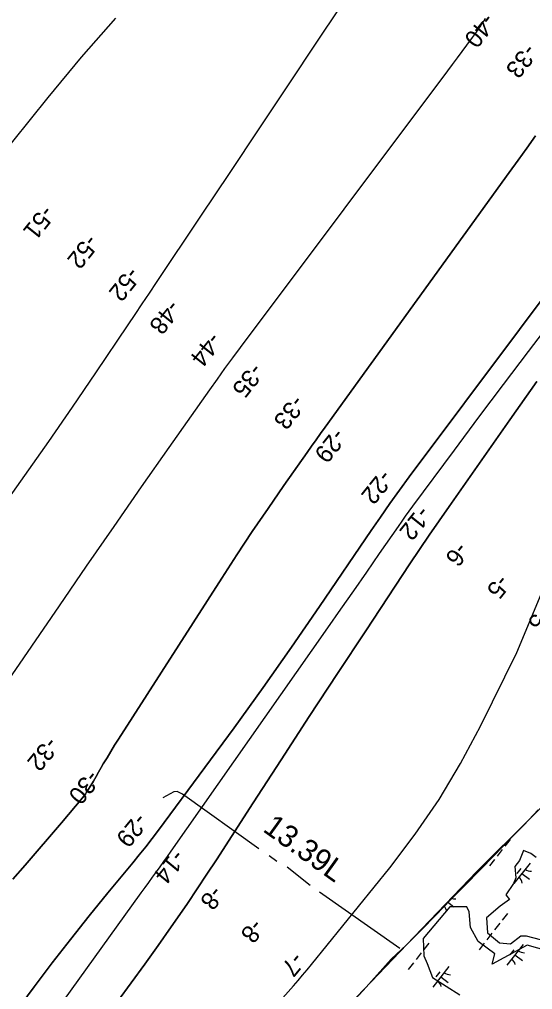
# Model space of a CAD drawing. Extents: x 3896831 to 3918110, y 171006 to 193349.
# Drawn here: x 3909708 to 3910688, y 181692 to 183545 of the extents above; entities that cross this region are included whole.
import ezdxf

# ---------------------------------------------------------------- set-up
doc = ezdxf.new("R2010")
doc.units = 0
for name, color, linetype in [('V-GRID-MAJR', 7, 'Continuous'), ('V-LEVE-TOET', 7, 'Continuous'), ('V-RIVR-EDGE', 7, 'Continuous'), ('V-RIVR-RANG', 7, 'Continuous'), ('V-RRAP-FSHR', 7, 'Continuous'), ('V-STRM-FMON', 7, 'Continuous'), ('V-TOPO-DPTH', 7, 'Continuous'), ('V-TOPO-MAJR', 7, 'Continuous'), ('V-TOPO-MINR', 7, 'Continuous'), ('V-WETL-SWMP', 7, 'Continuous')]:
    doc.layers.add(name, color=color, linetype=linetype)

msp = doc.modelspace()

# ---------------------------------------------------------------- linework, layer by layer
at = {"layer": 'V-GRID-MAJR'}
msp.add_spline([(3909752.8, 175802), (3909660.5, 181175.4), (3909556.5, 187235.6), (3909500.7, 190486.2)], degree=3, dxfattribs=at)
at = {"layer": 'V-LEVE-TOET'}
for p, q in [((3910200.2, 181936.9), (3910185.5, 181947.9)), ((3910263.7, 181891.2), (3910219.7, 181925.8)), ((3910434.7, 181770.8), (3910281.5, 181878.1))]:
    msp.add_line(p, q, dxfattribs=at)
msp.add_lwpolyline([(3910165.8, 181961.2), (3910019.7, 182065.5), (3910009.4, 182070.4), (3910003, 182070), (3909982, 182058.3)], dxfattribs=at)
at = {"layer": 'V-RIVR-EDGE'}
for points in [[(3910694.8, 181944.3), (3910684.7, 181952.2), (3910671.1, 181957.9), (3910663.2, 181938.7), (3910654.2, 181927.4), (3910656.4, 181905.9), (3910651.9, 181894.7), (3910637.3, 181873.2), (3910644, 181864.2), (3910626, 181851.8), (3910600, 181829.2), (3910602.3, 181801), (3910624.8, 181781.8), (3910646.3, 181779.5), (3910665.5, 181795.3), (3910675.6, 181795.3), (3910717.4, 181784.1)], [(3910718.5, 181766), (3910677.9, 181777.3), (3910611.3, 181741.2), (3910615.8, 181760.4), (3910584.2, 181784.1), (3910569.5, 181811.1), (3910567.3, 181840.5), (3910562.8, 181850.6), (3910530, 181850.6), (3910479.3, 181789.7), (3910480.4, 181757), (3910487.2, 181742.3), (3910497.3, 181715.2), (3910549.2, 181682.5)]]:
    msp.add_lwpolyline(points, dxfattribs=at)
at = {"layer": 'V-RRAP-FSHR'}
msp.add_lwpolyline([(3910095.3, 181395.6), (3910122.2, 181424.6), (3910149.2, 181454.2), (3910176.1, 181483.7), (3910203.1, 181513.2), (3910230.4, 181542.8), (3910256.9, 181572.4), (3910283.8, 181602.4), (3910310.7, 181631.6), (3910337.6, 181661.3), (3910364.5, 181690.9), (3910391.4, 181720.5), (3910418.3, 181750.7), (3910447.4, 181777.5), (3910475.5, 181805.9), (3910503.5, 181834.5), (3910531.5, 181863.6), (3910559.5, 181891.7), (3910587.4, 181920.4), (3910615.3, 181949.2), (3910643.1, 181977.7), (3910671.4, 182006.4), (3910698.9, 182035.3)], dxfattribs=at)
at = {"layer": 'V-TOPO-DPTH'}
for points in [[(3909679.6, 182271), (3909784.7, 182424.7), (3909836.8, 182500.7), (3909889.2, 182576.5), (3909941.8, 182652.1), (3909994.6, 182727.6), (3910071.8, 182837.4), (3910086.3, 182857.8), (3910100.9, 182878.1), (3910115.7, 182898.3), (3910130.7, 182918.4), (3910526.2, 183446.5), (3910535.4, 183458.7), (3910544.5, 183471), (3910553.6, 183483.3), (3910562.7, 183495.5), (3910573.3, 183509.9), (3910577.1, 183515), (3910580.8, 183520.2), (3910584.4, 183525.4), (3910587.9, 183530.7), (3910591.5, 183536), (3910595, 183541.3), (3910598.5, 183546.7)], [(3909679.6, 182271), (3909784.7, 182424.7), (3909836.8, 182500.7), (3909889.2, 182576.5), (3909941.8, 182652.1), (3909994.6, 182727.6), (3910071.8, 182837.4), (3910086.3, 182857.8), (3910100.9, 182878.1), (3910115.7, 182898.3), (3910130.7, 182918.4), (3910526.2, 183446.5), (3910535.4, 183458.7), (3910544.5, 183471), (3910553.6, 183483.3), (3910562.7, 183495.5), (3910573.3, 183509.9), (3910577.1, 183515), (3910580.8, 183520.2), (3910584.4, 183525.4), (3910587.9, 183530.7), (3910591.5, 183536), (3910595, 183541.3), (3910598.5, 183546.7)], [(3909695.8, 181903.2), (3909719.3, 181929.9), (3909742.6, 181956.7), (3909765.8, 181983.7), (3909788.8, 182010.8), (3909828.7, 182058.2), (3909831.6, 182061.8), (3909834.3, 182065.4), (3909836.8, 182069.2), (3909839.3, 182073), (3909844.7, 182082.1), (3909849.7, 182090.5), (3909854.7, 182099), (3909859.7, 182107.5), (3909864.6, 182116.1), (3909868.6, 182123.1), (3909875.7, 182135.1), (3909882.8, 182147.1), (3909890.1, 182158.9), (3909897.5, 182170.7), (3910094.6, 182477.8), (3910123.7, 182522.5), (3910153.1, 182567), (3910183.1, 182611), (3910213.4, 182654.9), (3910257.7, 182718), (3910266.2, 182730.1), (3910274.7, 182742.1), (3910283.3, 182754.1), (3910291.9, 182766.1), (3910643.6, 183252.5), (3910660.4, 183275.7), (3910677.2, 183299), (3910693.9, 183322.2)], [(3910693.9, 183322.2), (3910677.2, 183299), (3910660.4, 183275.7), (3910643.6, 183252.5), (3910291.9, 182766.1), (3910283.3, 182754.1), (3910274.7, 182742.1), (3910266.2, 182730.1), (3910257.7, 182718), (3910213.4, 182654.9), (3910183.1, 182611), (3910153.1, 182567), (3910123.7, 182522.5), (3910094.6, 182477.8), (3909897.5, 182170.7), (3909890.1, 182158.9), (3909882.8, 182147.1), (3909875.7, 182135.1), (3909868.6, 182123.1), (3909864.6, 182116.1), (3909859.7, 182107.5), (3909854.7, 182099), (3909849.7, 182090.5), (3909844.7, 182082.1), (3909839.3, 182073), (3909836.8, 182069.2), (3909834.3, 182065.4), (3909831.6, 182061.8), (3909828.7, 182058.2), (3909788.8, 182010.8), (3909765.8, 181983.7), (3909742.6, 181956.7), (3909719.3, 181929.9), (3909695.8, 181903.2)], [(3909520.4, 181405.9), (3909736.7, 181697.7), (3909771, 181743.2), (3909805.7, 181788.3), (3909841.3, 181832.9), (3909877.3, 181877), (3909924.7, 181934.2), (3909937.2, 181949.6), (3909949.6, 181965.1), (3909961.7, 181980.8), (3909973.7, 181996.6), (3910062.6, 182116.3), (3910118.5, 182192.4), (3910173.7, 182269), (3910227.9, 182346.3), (3910281.5, 182424), (3910379.8, 182568.7), (3910397.6, 182594.5), (3910415.7, 182620.3), (3910434.1, 182645.7), (3910452.8, 182671), (3910873.6, 183233.6)], [(3910873.6, 183233.6), (3910452.8, 182671), (3910434.1, 182645.7), (3910415.7, 182620.3), (3910397.6, 182594.5), (3910379.8, 182568.7), (3910281.5, 182424), (3910227.9, 182346.3), (3910173.7, 182269), (3910118.5, 182192.4), (3910062.6, 182116.3), (3909973.7, 181996.6), (3909961.7, 181980.8), (3909949.6, 181965.1), (3909937.2, 181949.6), (3909924.7, 181934.2), (3909877.3, 181877), (3909841.3, 181832.9), (3909805.7, 181788.3), (3909771, 181743.2), (3909736.7, 181697.7), (3909520.4, 181405.9)], [(3910696.1, 182853.3), (3910644.5, 182780.4), (3910528.6, 182614.9), (3910509.7, 182587.6), (3910490.9, 182560.2), (3910472.4, 182532.7), (3910453.9, 182505.1), (3910369.5, 182377.5), (3910315.5, 182295.6), (3910261.7, 182213.5), (3910208.1, 182131.3), (3910154.7, 182049), (3910084.4, 181940.3), (3910066.2, 181912.4), (3910047.8, 181884.6), (3910029.1, 181856.9), (3910010.2, 181829.5), (3909998.2, 181812.2), (3909973.1, 181776.4), (3909947.7, 181740.7), (3909921.9, 181705.2), (3909895.9, 181669.9)]]:
    msp.add_lwpolyline(points, dxfattribs=at)
at = {"layer": 'V-TOPO-MAJR'}
for points in [[(3909672.8, 182609), (3909719, 182673.7), (3909764.7, 182738.6), (3909809.8, 182804), (3909854.4, 182869.7), (3909915.9, 182961.3), (3909929.5, 182981.5), (3909943, 183001.7), (3909956.5, 183021.9), (3909970.1, 183042.1), (3910054.7, 183168.7), (3910110.5, 183252.2), (3910166.2, 183335.8), (3910221.9, 183419.4), (3910277.6, 183503), (3910361.5, 183629.2)], [(3909892, 183547.2), (3909826.4, 183472.3), (3909762.5, 183395.7), (3909661.1, 183269.5)]]:
    msp.add_lwpolyline(points, dxfattribs=at)
at = {"layer": 'V-TOPO-MINR'}
for points in [[(3909679.6, 182271), (3909784.7, 182424.7), (3909836.8, 182500.7), (3909889.2, 182576.5), (3909941.8, 182652.1), (3909994.6, 182727.6), (3910071.8, 182837.4), (3910086.3, 182857.8), (3910100.9, 182878.1), (3910115.7, 182898.3), (3910130.7, 182918.4), (3910526.2, 183446.5), (3910535.4, 183458.7), (3910544.5, 183471), (3910553.6, 183483.3), (3910562.7, 183495.5), (3910573.3, 183509.9), (3910577.1, 183515), (3910580.8, 183520.2), (3910584.4, 183525.4), (3910587.9, 183530.7), (3910591.5, 183536), (3910595, 183541.3), (3910598.5, 183546.7)], [(3909695.8, 181903.2), (3909719.3, 181929.9), (3909742.6, 181956.7), (3909765.8, 181983.7), (3909788.8, 182010.8), (3909828.7, 182058.2), (3909831.6, 182061.8), (3909834.3, 182065.4), (3909836.8, 182069.2), (3909839.3, 182073), (3909844.7, 182082.1), (3909849.7, 182090.5), (3909854.7, 182099), (3909859.7, 182107.5), (3909864.6, 182116.1), (3909868.6, 182123.1), (3909875.7, 182135.1), (3909882.8, 182147.1), (3909890.1, 182158.9), (3909897.5, 182170.7), (3910094.6, 182477.8), (3910123.7, 182522.5), (3910153.1, 182567), (3910183.1, 182611), (3910213.4, 182654.9), (3910257.7, 182718), (3910266.2, 182730.1), (3910274.7, 182742.1), (3910283.3, 182754.1), (3910291.9, 182766.1), (3910643.6, 183252.5), (3910660.4, 183275.7), (3910677.2, 183299), (3910693.9, 183322.2)], [(3909520.4, 181405.9), (3909736.7, 181697.7), (3909771, 181743.2), (3909805.7, 181788.3), (3909841.3, 181832.9), (3909877.3, 181877), (3909924.7, 181934.2), (3909937.2, 181949.6), (3909949.6, 181965.1), (3909961.7, 181980.8), (3909973.7, 181996.6), (3910062.6, 182116.3), (3910118.5, 182192.4), (3910173.7, 182269), (3910227.9, 182346.3), (3910281.5, 182424), (3910379.8, 182568.7), (3910397.6, 182594.5), (3910415.7, 182620.3), (3910434.1, 182645.7), (3910452.8, 182671), (3910873.6, 183233.6)], [(3909762.1, 181628), (3909941.2, 181877.3), (3909948.4, 181887.2), (3909955.5, 181897.1), (3909962.7, 181907), (3909969.9, 181916.9), (3909977, 181926.8), (3909984.2, 181936.7), (3909991.3, 181946.7), (3909998.3, 181956.7), (3910297, 182382.9), (3910321.8, 182418.4), (3910346.7, 182453.9), (3910371.4, 182489.5), (3910396.2, 182525.1), (3910432, 182576.7), (3910438.9, 182586.5), (3910445.8, 182596.2), (3910452.8, 182605.9), (3910459.8, 182615.5), (3910538.9, 182722.3), (3910585.7, 182785.1), (3910632.8, 182847.8), (3910680.1, 182910.3), (3910727.7, 182972.6)], [(3908993.8, 179918), (3909778.7, 181196.5), (3909782.4, 181202), (3909786.6, 181207.3), (3909882.7, 181311), (3909935.2, 181368.1), (3909987.5, 181425.3), (3910039.4, 181483), (3910091, 181540.8), (3910231.6, 181699.3), (3910240.4, 181709.4), (3910249.1, 181719.6), (3910257.8, 181729.8), (3910266.3, 181740.2), (3910415.7, 181924.6), (3910464.3, 181988.8), (3910509.8, 182055), (3910550.8, 182124.1), (3910588.8, 182195.1), (3910657.9, 182335.8), (3910918.8, 182961.5)], [(3909895.9, 181669.9), (3909921.9, 181705.2), (3909947.7, 181740.7), (3909973.1, 181776.4), (3909998.2, 181812.2), (3910010.2, 181829.5), (3910029.1, 181856.9), (3910047.8, 181884.6), (3910066.2, 181912.4), (3910084.4, 181940.3), (3910154.7, 182049), (3910208.1, 182131.3), (3910261.7, 182213.5), (3910315.5, 182295.6), (3910369.5, 182377.5), (3910453.9, 182505.1), (3910472.4, 182532.7), (3910490.9, 182560.2), (3910509.7, 182587.6), (3910528.6, 182614.9), (3910644.5, 182780.4), (3910696.1, 182853.3)]]:
    msp.add_lwpolyline(points, dxfattribs=at)
at = {"layer": 'V-WETL-SWMP'}
for p, q in [((3910683.8, 182019.1), (3910763.8, 182098.7)), ((3910582, 181918), (3910683.8, 182019.1)), ((3910645.1, 181978.8), (3910635.3, 181966.2)), ((3910630.3, 181959.9), (3910620.5, 181947.3)), ((3910615.5, 181941), (3910605.7, 181928.4)), ((3910683.4, 181933.9), (3910652.5, 181894.6)), ((3910461.9, 181793.3), (3910582, 181918)), ((3910665.6, 181923.7), (3910658.2, 181914.3)), ((3910667.9, 181914.3), (3910682.1, 181903.2)), ((3910525.8, 181859.6), (3910537.8, 181850.2)), ((3910640.2, 181837.8), (3910630.3, 181825.2)), ((3910625.4, 181818.9), (3910615.5, 181806.3)), ((3910251, 181572.5), (3910461.9, 181793.3)), ((3910610.6, 181800), (3910600.7, 181787.4)), ((3910490.3, 181781.2), (3910480.5, 181768.6)), ((3910595.8, 181781.1), (3910585.9, 181768.5)), ((3910669.9, 181778.4), (3910639.1, 181739)), ((3910652.1, 181768.2), (3910644.7, 181758.7)), ((3910475.5, 181762.3), (3910465.7, 181749.8)), ((3910654.5, 181758.7), (3910668.7, 181747.6)), ((3910460.7, 181743.5), (3910450.9, 181730.9)), ((3910528.5, 181736.4), (3910497.7, 181697.1)), ((3910510.8, 181726.2), (3910503.4, 181716.8)), ((3910513.1, 181716.7), (3910527.3, 181705.6))]:
    msp.add_line(p, q, dxfattribs=at)
for centre, start, end in [((3910685.2, 181935.9), 231.1403, 272.6839), ((3910651.1, 181892.4), 11.1403, 52.6839), ((3910540.8, 181882.9), 243.6764, 272.6839), ((3910506.7, 181839.4), 11.1403, 47.0013), ((3910671.7, 181780.3), 231.1403, 272.6839), ((3910637.7, 181736.8), 11.1403, 52.6839), ((3910496.3, 181694.9), 11.1403, 52.6839), ((3910530.4, 181738.3), 231.1403, 272.6839)]:
    msp.add_arc(centre, 17.6, start, end, dxfattribs=at)

# ---------------------------------------------------------------- texts
at = {"layer": 'V-RIVR-RANG'}
for s, rotation, p in [('-40', 231.4478, (3910596, 183558.7)), ('-33', 231.4478, (3910675.3, 183500.5)), ('-51', 231.4194, (3909754, 183192)), ('-52', 231.4194, (3909838.2, 183136.6)), ('-52', 231.4194, (3909917.6, 183074.5)), ('-48', 231.4194, (3909994.8, 183011.4)), ('-44', 231.4194, (3910073, 182949.7)), ('-35', 231.4194, (3910153, 182890.6)), ('-33', 231.4194, (3910232.2, 182829.7)), ('-29', 231.4194, (3910310.1, 182766.2)), ('-22', 231.2783, (3910399.4, 182687.1)), ('-12', 231.2783, (3910472.3, 182618.2)), ('-6', 231.2783, (3910544.8, 182548.8)), ('-5', 231.2783, (3910623.5, 182487.1)), ('-5', 231.2783, (3910701.7, 182424.7)), ('-32', 230.6577, (3909762.4, 182177.4)), ('-30', 230.6577, (3909841, 182113.9)), ('-29', 230.5183, (3909932.2, 182032)), ('-14', 230.5183, (3910004.2, 181962)), ('-8', 230.5183, (3910076.9, 181893)), ('-8', 230.5183, (3910154.2, 181829.7)), ('-7', 230.5183, (3910231.4, 181766.1))]:
    msp.add_text(s, height=33.5, rotation=rotation, dxfattribs=at).set_placement(p)
at = {"layer": 'V-STRM-FMON'}
msp.add_text('13.39L', height=42, rotation=324.3488, dxfattribs=at).set_placement((3910171.3, 181995.7))

doc.saveas('drawing.dxf')
